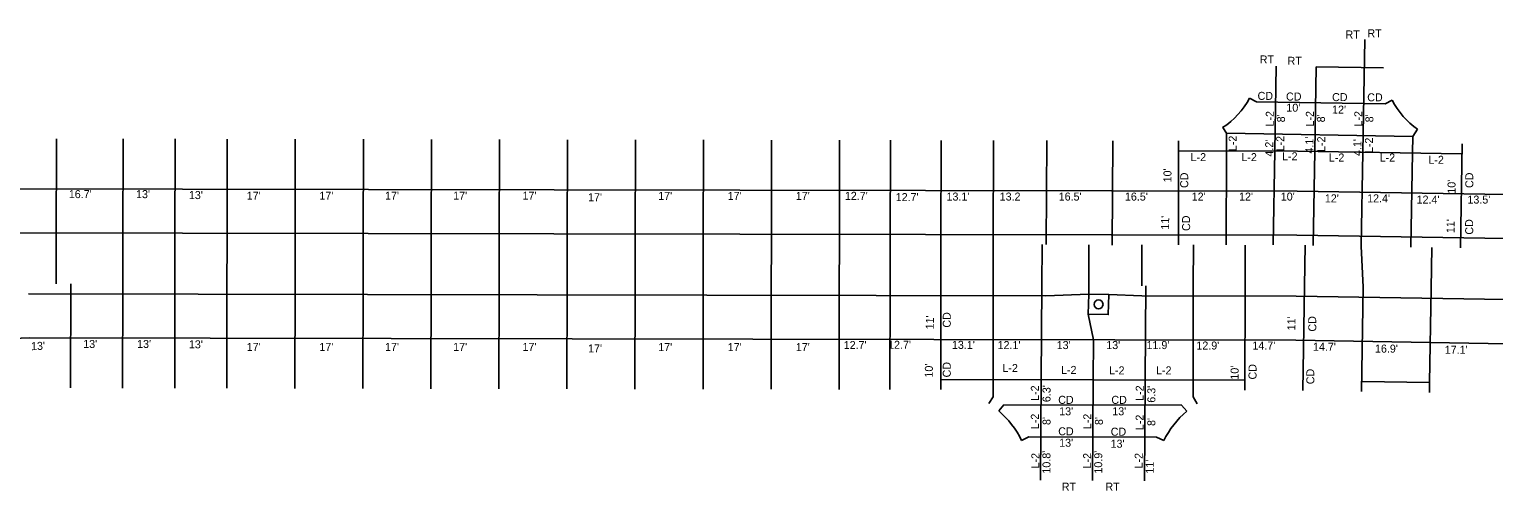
# Model space of a CAD drawing. Extents: x 4995357 to 4999033, y 3881202 to 3881750.
# Drawn here: x 4996092.1 to 4996458, y 3881618.7 to 3881733.9 of the extents above; entities that cross this region are included whole.
import ezdxf

# ---------------------------------------------------------------- set-up
doc = ezdxf.new("R2010")
doc.units = 0
for name, color, linetype in [('dsn3DCenterLine', 7, 'Continuous'), ('dsn3DCurbFormgrade', 7, 'Continuous'), ('dsn3DCurbTop', 7, 'Continuous'), ('dsn3DDNC', 7, 'Continuous'), ('dsn3DExistingPvmtBtm', 7, 'Continuous'), ('dsn3DGroundLineIntercept', 7, 'Continuous'), ('dsn3DIntakeWell', 7, 'Continuous')]:
    doc.layers.add(name, color=color, linetype=linetype)

msp = doc.modelspace()

# ---------------------------------------------------------------- linework, layer by layer
at = {"layer": 'dsn3DCurbFormgrade'}
for p, q in [((4996413.62, 3881724.58), (4996430.42, 3881724.3)), ((4996098.77, 3881680.59), (4996098.82, 3881706.59)), ((4996115.49, 3881706.55), (4996115.44, 3881680.55)), ((4996128.5, 3881706.53), (4996128.45, 3881680.53)), ((4996141.52, 3881706.51), (4996141.47, 3881680.51)), ((4996158.52, 3881706.48), (4996158.47, 3881680.48)), ((4996175.52, 3881706.44), (4996175.47, 3881680.44)), ((4996192.52, 3881706.41), (4996192.47, 3881680.41)), ((4996209.52, 3881706.38), (4996209.47, 3881680.38)), ((4996226.52, 3881706.35), (4996226.47, 3881680.35)), ((4996243.52, 3881706.32), (4996243.47, 3881680.32)), ((4996260.52, 3881706.29), (4996260.47, 3881680.29)), ((4996277.52, 3881706.26), (4996277.47, 3881680.26)), ((4996294.52, 3881706.23), (4996294.47, 3881680.23)), ((4996307.21, 3881706.2), (4996307.16, 3881680.2)), ((4996319.85, 3881680.18), (4996319.9, 3881706.18)), ((4996332.93, 3881680.16), (4996332.98, 3881706.16)), ((4996346.27, 3881706.13), (4996346.11, 3881680.13)), ((4996362.77, 3881706.03), (4996362.61, 3881680.03)), ((4996379.22, 3881706.07), (4996379.17, 3881680.07)), ((4996450.07, 3881705.33), (4996449.64, 3881679.34)), ((4996391.16, 3881703.55), (4996391.12, 3881680.05)), ((4996402.88, 3881680.11), (4996403.27, 3881703.53)), ((4996412.88, 3881679.95), (4996413.27, 3881703.44)), ((4996424.88, 3881679.75), (4996425.27, 3881703.25)), ((4996437.65, 3881703.04), (4996437.26, 3881679.54)), ((4996102.41, 3881670.33), (4996102.36, 3881644.33)), ((4996115.42, 3881670.3), (4996115.37, 3881644.3)), ((4996128.44, 3881670.28), (4996128.39, 3881644.28)), ((4996141.45, 3881670.26), (4996141.4, 3881644.26)), ((4996158.45, 3881670.23), (4996158.4, 3881644.23)), ((4996175.45, 3881670.19), (4996175.4, 3881644.19)), ((4996192.45, 3881670.16), (4996192.4, 3881644.16)), ((4996209.45, 3881670.13), (4996209.4, 3881644.13)), ((4996226.45, 3881670.1), (4996226.4, 3881644.1)), ((4996243.45, 3881670.07), (4996243.4, 3881644.07)), ((4996260.45, 3881670.04), (4996260.4, 3881644.04)), ((4996277.45, 3881670.01), (4996277.4, 3881644.01)), ((4996294.45, 3881669.98), (4996294.4, 3881643.98)), ((4996307.14, 3881669.95), (4996307.09, 3881643.95)), ((4996319.78, 3881643.93), (4996319.83, 3881669.93)), ((4996332.87, 3881646.41), (4996332.91, 3881669.91)), ((4996345.05, 3881669.88), (4996344.9, 3881646.38)), ((4996356.77, 3881669.86), (4996356.76, 3881667.76)), ((4996371.05, 3881669.84), (4996370.9, 3881646.34)), ((4996382.84, 3881646.31), (4996382.89, 3881669.81)), ((4996395.79, 3881643.79), (4996395.83, 3881669.79)), ((4996410.71, 3881669.73), (4996410.28, 3881643.74)), ((4996425.38, 3881669.49), (4996424.95, 3881643.49)), ((4996442.33, 3881669.21), (4996441.94, 3881645.71)), ((4996356.67, 3881662.76), (4996357.96, 3881656.36)), ((4996357.96, 3881656.36), (4996357.9, 3881646.36)), ((4996335.57, 3881640.13), (4996379.99, 3881640.05)), ((4996341.79, 3881632.12), (4996373.74, 3881632.06))]:
    msp.add_line(p, q, dxfattribs=at)
at = {"layer": 'dsn3DCurbTop'}
for p, q in [((4996396.95, 3881716.75), (4996398.72, 3881715.82)), ((4996432.61, 3881716.2), (4996430.83, 3881715.28)), ((4996390.24, 3881709.36), (4996391.17, 3881707.94)), ((4996438.95, 3881708.94), (4996437.72, 3881707.17)), ((4996098.77, 3881680.59), (4996098.75, 3881670.34)), ((4996115.44, 3881680.55), (4996115.42, 3881670.3)), ((4996128.44, 3881670.28), (4996128.45, 3881680.53)), ((4996141.47, 3881680.51), (4996141.45, 3881670.26)), ((4996158.45, 3881670.23), (4996158.47, 3881680.48)), ((4996175.47, 3881680.44), (4996175.45, 3881670.19)), ((4996192.45, 3881670.16), (4996192.47, 3881680.41)), ((4996209.45, 3881670.13), (4996209.47, 3881680.38)), ((4996226.47, 3881680.35), (4996226.45, 3881670.1)), ((4996243.45, 3881670.07), (4996243.47, 3881680.32)), ((4996260.47, 3881680.29), (4996260.45, 3881670.04)), ((4996277.45, 3881670.01), (4996277.47, 3881680.26)), ((4996294.45, 3881669.98), (4996294.47, 3881680.23)), ((4996307.16, 3881680.2), (4996307.14, 3881669.95)), ((4996319.83, 3881669.93), (4996319.85, 3881680.18)), ((4996332.93, 3881680.16), (4996332.91, 3881669.91)), ((4996345.11, 3881680.13), (4996345.05, 3881669.88)), ((4996356.77, 3881669.86), (4996356.79, 3881680.11)), ((4996370.05, 3881669.84), (4996370.06, 3881680.09)), ((4996382.89, 3881669.81), (4996382.91, 3881680.06)), ((4996395.83, 3881669.79), (4996395.85, 3881680.04)), ((4996410.71, 3881669.73), (4996410.88, 3881679.98)), ((4996424.88, 3881679.75), (4996425.38, 3881669.49)), ((4996442.33, 3881669.21), (4996442.5, 3881679.46)), ((4996331.79, 3881640.43), (4996332.86, 3881642.12)), ((4996383.89, 3881640.41), (4996382.84, 3881642.11)), ((4996334.28, 3881638.61), (4996335.57, 3881640.13)), ((4996381.27, 3881638.52), (4996379.99, 3881640.05)), ((4996339.99, 3881631.25), (4996341.79, 3881632.12)), ((4996375.54, 3881631.18), (4996373.74, 3881632.06))]:
    msp.add_line(p, q, dxfattribs=at)
at = {"layer": 'dsn3DDNC'}
for p, q in [((4996425.27, 3881703.25), (4996425.73, 3881731.36)), ((4996403.27, 3881703.53), (4996403.62, 3881724.74)), ((4996413.27, 3881703.44), (4996413.62, 3881724.58)), ((4996391.17, 3881707.94), (4996391.16, 3881703.55)), ((4996437.72, 3881707.17), (4996437.65, 3881703.04)), ((4996379.21, 3881703.57), (4996408.95, 3881703.52)), ((4996408.95, 3881703.52), (4996450.03, 3881702.83)), ((4995693.02, 3881694.83), (4996408.86, 3881693.52)), ((4996408.86, 3881693.52), (4996644.25, 3881689.61)), ((4995693.07, 3881683.83), (4996408.76, 3881682.52)), ((4996408.76, 3881682.52), (4996644.28, 3881678.6)), ((4996091.85, 3881667.85), (4996346.03, 3881667.38)), ((4996346.03, 3881667.38), (4996356.76, 3881667.76)), ((4996361.76, 3881667.68), (4996370.03, 3881667.34)), ((4996370.03, 3881667.34), (4996408.62, 3881667.27)), ((4996408.62, 3881667.27), (4996674.65, 3881662.85)), ((4996010.8, 3881653.75), (4996092.05, 3881656.85)), ((4996092.05, 3881656.85), (4996408.52, 3881656.27)), ((4996408.52, 3881656.27), (4997479.7, 3881638.47)), ((4996319.79, 3881646.43), (4996395.79, 3881646.29)), ((4996332.86, 3881642.12), (4996332.87, 3881646.41)), ((4996344.9, 3881646.38), (4996344.74, 3881621.27)), ((4996357.9, 3881646.36), (4996357.74, 3881621.19)), ((4996370.9, 3881646.34), (4996370.74, 3881621.11)), ((4996382.84, 3881642.11), (4996382.84, 3881646.31))]:
    msp.add_line(p, q, dxfattribs=at)
at = {"layer": 'dsn3DExistingPvmtBtm'}
for p, q in [((4996441.94, 3881645.71), (4996424.99, 3881645.99)), ((4996441.9, 3881643.21), (4996441.94, 3881645.71))]:
    msp.add_line(p, q, dxfattribs=at)
msp.add_lwpolyline([(4996361.76, 3881667.68), (4996361.67, 3881662.68), (4996356.67, 3881662.76), (4996356.76, 3881667.76)], close=True, dxfattribs=at)
msp.add_circle((4996359.22, 3881665.22), 1.12, dxfattribs=at)
at = {"layer": 'dsn3DGroundLineIntercept'}
for p, q in [((4996398.72, 3881715.82), (4996430.83, 3881715.28)), ((4996391.17, 3881707.94), (4996437.72, 3881707.17))]:
    msp.add_line(p, q, dxfattribs=at)
at = {"layer": 'dsn3DIntakeWell'}
for points in [[(4996396.95, 3881716.75), (4996398.72, 3881715.82), (4996430.83, 3881715.28), (4996432.61, 3881716.2)], [(4996438.95, 3881708.94), (4996437.72, 3881707.17), (4996391.17, 3881707.94), (4996390.24, 3881709.36)], [(4996334.28, 3881638.61), (4996335.57, 3881640.13), (4996379.99, 3881640.05), (4996381.27, 3881638.52)], [(4996375.54, 3881631.18), (4996373.74, 3881632.06), (4996341.79, 3881632.12), (4996339.99, 3881631.25)]]:
    msp.add_lwpolyline(points, dxfattribs=at)
for centre, radius, start, end in [((4996379.25, 3881726.07), 20, 303.3188, 332.2235), ((4996450.41, 3881725.33), 20, 207.1702, 235.0605), ((4996319.74, 3881621.43), 22.5, 25.8772, 49.7692), ((4996395.74, 3881621.29), 22.5, 130.0206, 153.9126)]:
    msp.add_arc(centre, radius, start, end, dxfattribs=at)

# ---------------------------------------------------------------- texts
at = {"layer": 'dsn3DCenterLine'}
for s, p in [('RT', (4996420.93, 3881731.62)), ('RT', (4996426.41, 3881731.92)), ('RT', (4996399.5, 3881725.39)), ('RT', (4996406.46, 3881725.05)), ('CD', (4996398.96, 3881716.29)), ('CD', (4996406.07, 3881716.13)), ('CD', (4996417.58, 3881715.98)), ('CD', (4996426.36, 3881715.93)), ('L-2', (4996382.22, 3881700.99)), ('L-2', (4996394.92, 3881700.99)), ('L-2', (4996405.08, 3881701.2)), ('L-2', (4996416.77, 3881700.9)), ('L-2', (4996429.47, 3881700.9)), ('L-2', (4996441.64, 3881700.32)), ("16.7'", (4996101.93, 3881691.75)), ("13'", (4996118.73, 3881691.75)), ("13'", (4996131.93, 3881691.52)), ("17'", (4996146.38, 3881691.36)), ("17'", (4996164.54, 3881691.36)), ("17'", (4996180.94, 3881691.36)), ("17'", (4996197.97, 3881691.36)), ("17'", (4996215.29, 3881691.36)), ("17'", (4996249.21, 3881691.32)), ("17'", (4996266.57, 3881691.32)), ("17'", (4996283.58, 3881691.32)), ("12.7'", (4996295.84, 3881691.32)), ("13.1'", (4996321.24, 3881691.14)), ('13.2', (4996334.52, 3881691.14)), ("16.5'", (4996349.27, 3881691.14)), ("16.5'", (4996365.82, 3881691.14)), ("12'", (4996382.5, 3881691.14)), ("12'", (4996394.34, 3881691.14)), ("10'", (4996404.76, 3881691.14)), ("17'", (4996231.68, 3881690.99)), ("12.7'", (4996308.54, 3881691.01)), ("12'", (4996415.77, 3881690.69)), ("12.4'", (4996426.34, 3881690.69)), ("12.4'", (4996438.7, 3881690.39)), ("13.5'", (4996451.4, 3881690.39)), ("13'", (4996131.93, 3881654.23)), ("17'", (4996146.38, 3881653.59)), ("17'", (4996164.54, 3881653.59)), ("17'", (4996180.94, 3881653.59)), ("17'", (4996197.97, 3881653.59)), ("17'", (4996215.29, 3881653.59)), ("17'", (4996231.68, 3881653.22)), ("17'", (4996249.21, 3881653.55)), ("17'", (4996266.57, 3881653.55)), ("17'", (4996283.58, 3881653.55)), ("12.7'", (4996295.55, 3881654.06)), ("12.7'", (4996306.64, 3881654.12)), ("13.1'", (4996322.59, 3881654.1)), ("12.1'", (4996334, 3881654.05)), ("13'", (4996348.77, 3881654.05)), ("13'", (4996361.15, 3881654.05)), ("11.9'", (4996371.21, 3881654.05)), ("12.9'", (4996383.67, 3881653.94)), ("14.7'", (4996397.68, 3881653.94)), ("14.7'", (4996412.81, 3881653.63)), ("16.9'", (4996428.3, 3881653.17)), ("17.1'", (4996445.73, 3881652.88)), ('L-2', (4996335.2, 3881648.32)), ('L-2', (4996349.85, 3881647.84)), ('L-2', (4996361.85, 3881647.73)), ('L-2', (4996373.59, 3881647.73)), ('CD', (4996349.15, 3881640.37)), ('CD', (4996362.43, 3881640.37)), ("13'", (4996349.39, 3881637.51)), ("13'", (4996362.66, 3881637.51)), ('CD', (4996349.15, 3881632.51)), ("13'", (4996349.39, 3881629.66)), ('CD', (4996362.26, 3881632.41)), ("13'", (4996362.24, 3881629.41)), ('RT', (4996350.04, 3881618.68)), ('RT', (4996360.94, 3881618.68))]:
    msp.add_text(s, height=2, dxfattribs=at).set_placement(p)
for s, rotation, p in [("10'", 359.0482, (4996406.14, 3881713.38)), ('L-2', 90, (4996403.02, 3881709.64)), ("8'", 90, (4996405.81, 3881710.68)), ('L-2', 90, (4996413.02, 3881709.64)), ("8'", 90, (4996415.8, 3881710.68)), ("12'", 359.0482, (4996417.56, 3881712.9)), ('L-2', 90, (4996425.12, 3881709.64)), ("8'", 90, (4996427.9, 3881710.68)), ('L-2', 90, (4996393.74, 3881703.48)), ("4.2'", 90, (4996402.86, 3881702.13)), ('L-2', 90, (4996405.63, 3881703.43)), ("4.1'", 90, (4996412.92, 3881702.89)), ('L-2', 90, (4996415.86, 3881703.29)), ("4.1'", 90, (4996424.91, 3881702.27)), ('L-2', 90, (4996427.81, 3881703)), ("10'", 89.7464, (4996377.44, 3881695.68)), ('CD', 90, (4996381.63, 3881694.28)), ('CD', 90.7912, (4996452.89, 3881694.29)), ("10'", 89.7464, (4996448.42, 3881692.86)), ("11'", 89.7464, (4996376.86, 3881683.86)), ('CD', 90.7912, (4996382.12, 3881683.56)), ("11'", 89.7464, (4996448.18, 3881683)), ('CD', 90.7912, (4996452.86, 3881682.64)), ("11'", 89.0288, (4996318.04, 3881658.94)), ('CD', 90.0736, (4996322.3, 3881659.4)), ("11'", 89.7464, (4996408.4, 3881658.73)), ('CD', 90.7912, (4996413.65, 3881658.43)), ("13'", 2.1855, (4996092.53, 3881653.76)), ("13'", 359.7162, (4996105.52, 3881654.34)), ("13'", 359.7162, (4996118.99, 3881654.34)), ("10'", 89.0288, (4996317.79, 3881646.92)), ('CD', 90.0736, (4996322.3, 3881646.97)), ("10'", 89.0288, (4996394.19, 3881646.4)), ('CD', 90.0736, (4996398.7, 3881646.45)), ('CD', 90.7912, (4996413.16, 3881645.28)), ('L-2', 90, (4996344.31, 3881641.11)), ("6.3'", 90, (4996347.23, 3881640.8)), ('L-2', 90, (4996370.51, 3881641.11)), ("6.3'", 90, (4996373.42, 3881640.65)), ('L-2', 90, (4996344.31, 3881634.04)), ("8'", 90, (4996347.23, 3881635.08)), ('L-2', 90, (4996357.41, 3881634.04)), ("8'", 90, (4996360.32, 3881635.08)), ('L-2', 90, (4996370.49, 3881633.8)), ("8'", 90, (4996373.41, 3881634.84)), ('L-2', 90, (4996344.44, 3881624.24)), ("10.8'", 90, (4996347.21, 3881622.95)), ('L-2', 90, (4996357.38, 3881624.24)), ("10.9'", 90, (4996360.15, 3881622.95)), ('L-2', 90, (4996370.26, 3881624.24)), ("11'", 90, (4996373.03, 3881622.95))]:
    msp.add_text(s, height=2, rotation=rotation, dxfattribs=at).set_placement(p)

doc.saveas('drawing.dxf')
